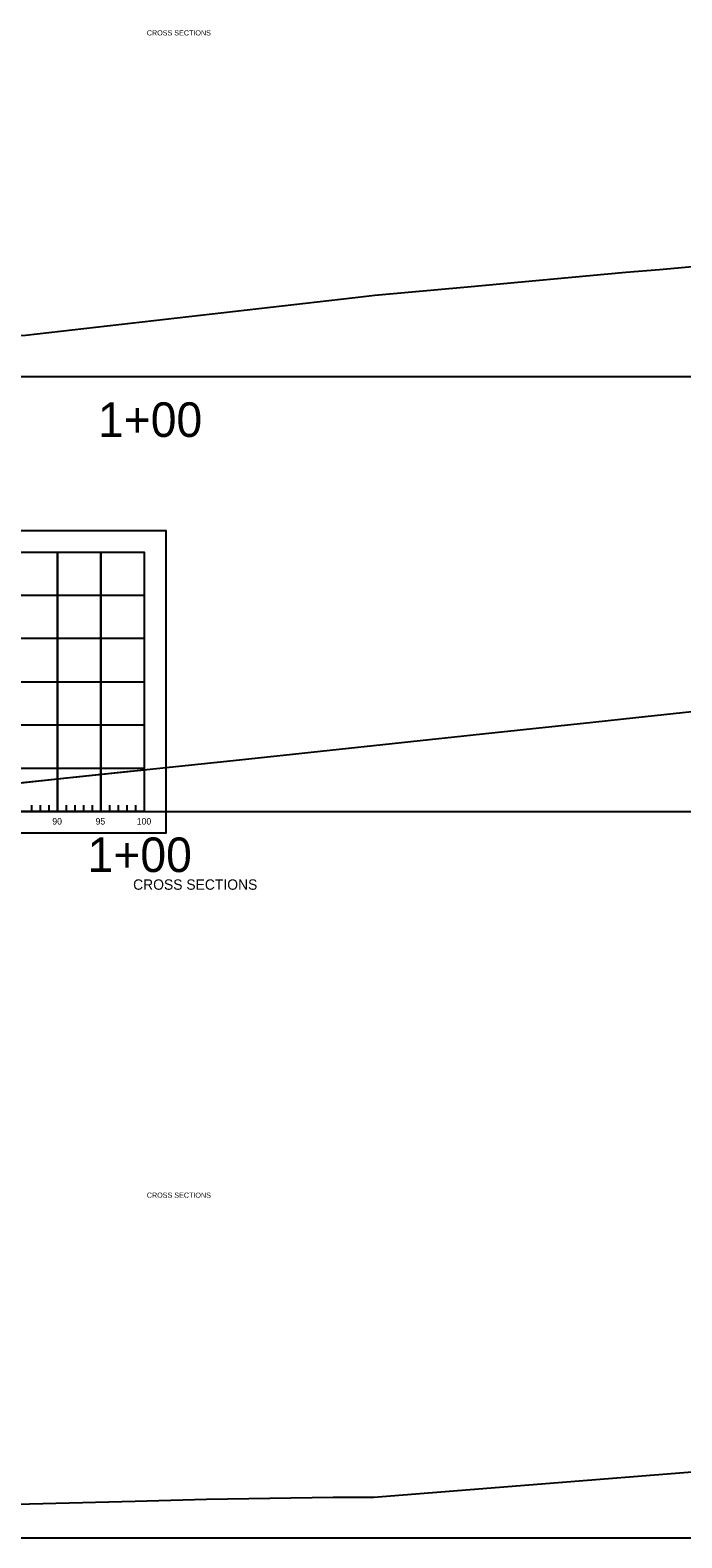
# Model space of a CAD drawing. Extents: x 1578769 to 1579225, y 724002 to 724828.
# Drawn here: x 1578926.9 to 1579002.2, y 724303.2 to 724477.5 of the extents above; entities that cross this region are included whole.
import ezdxf

# ---------------------------------------------------------------- set-up
doc = ezdxf.new("R2010")
doc.units = 0
for name, color, linetype in [('1', 7, 'Continuous'), ('Default', 7, 'Continuous'), ('Old_Level_1', 7, 'Continuous'), ('Old_Level_41', 7, 'Continuous'), ('Old_Level_42', 7, 'Continuous'), ('R_Border', 7, 'Continuous'), ('R_Exist Surface', 7, 'Continuous')]:
    doc.layers.add(name, color=color, linetype=linetype)

msp = doc.modelspace()

# ---------------------------------------------------------------- linework, layer by layer
at = {"layer": 'Default'}
for p, q in [((1578841.23, 724437.47), (1579141.23, 724437.47)), ((1578840.03, 724387.15), (1579140.03, 724387.15)), ((1578824.19, 724303.15), (1579224.19, 724303.15))]:
    msp.add_line(p, q, dxfattribs=at)
for points in [[(1578841.23, 724457.07), (1578842.26, 724457.06), (1578863.33, 724456.94), (1578874.29, 724456.89), (1578876.4, 724454.8), (1578883.17, 724446.78), (1578901.02, 724441.71), (1578903.45, 724441.03), (1578909.92, 724441.38), (1578926.32, 724442.25), (1578964.09, 724446.55), (1578966.7, 724446.87), (1578977.39, 724447.84), (1578995.69, 724449.51), (1578999.6, 724449.84), (1579038.5, 724453.37)], [(1578840.03, 724407.28), (1578843.97, 724407.18), (1578868.72, 724406.96), (1578870.69, 724406.94), (1578871.02, 724406.55), (1578881.3, 724394.25), (1578887.04, 724393.8), (1578904.53, 724392.22), (1578918.75, 724390.98), (1578924.86, 724390.39), (1578951.06, 724393.14), (1578979.15, 724396.13), (1578991.89, 724397.48), (1578996.87, 724398.01), (1579008.38, 724399.25), (1579066.25, 724403.44), (1579074.56, 724404.15)], [(1578822.94, 724322.15), (1578824.35, 724322.1), (1578827.25, 724322.09), (1578831.42, 724322.06), (1578836.82, 724322.03), (1578858.59, 724322.07), (1578861.13, 724322.07), (1578862.94, 724322.07), (1578882.45, 724322.01), (1578884.52, 724320.41), (1578890.39, 724312.8), (1578905.44, 724309.39), (1578918.12, 724306.85), (1578923.76, 724307), (1578939, 724307.39), (1578947.24, 724307.61), (1578961.87, 724307.85), (1578966.59, 724307.87), (1579023.72, 724312.41), (1579059.08, 724315.37), (1579126.24, 724320.04), (1579145.79, 724321.28)]]:
    msp.add_lwpolyline(points, dxfattribs=at)
at = {"layer": 'Old_Level_1'}
msp.add_lwpolyline([(1578815.03, 724419.65), (1578942.53, 724419.65), (1578942.53, 724384.65), (1578815.03, 724384.65)], close=True, dxfattribs=at)
msp.add_lwpolyline([(1578820.03, 724417.15), (1578940.03, 724417.15), (1578940.03, 724387.15), (1578820.03, 724387.15)], dxfattribs=at)
at = {"layer": 'Old_Level_41'}
for p, q in [((1578930.03, 724387.15), (1578930.03, 724417.15)), ((1578930.03, 724417.15), (1578930.03, 724387.15)), ((1578935.03, 724387.15), (1578935.03, 724417.15)), ((1578935.03, 724417.15), (1578935.03, 724387.15))]:
    msp.add_line(p, q, dxfattribs=at)
for points in [[(1578940.03, 724412.15), (1578820.03, 724412.15)], [(1578940.03, 724407.15), (1578820.03, 724407.15)], [(1578820.03, 724402.15), (1578940.03, 724402.15)], [(1578940.03, 724397.15), (1578820.03, 724397.15)], [(1578820.03, 724392.15), (1578940.03, 724392.15)]]:
    msp.add_lwpolyline(points, dxfattribs=at)
at = {"layer": 'Old_Level_42'}
for p, q in [((1578927.03, 724387.9), (1578927.03, 724387.15)), ((1578928.03, 724387.9), (1578928.03, 724387.15)), ((1578929.03, 724387.9), (1578929.03, 724387.15)), ((1578931.03, 724387.9), (1578931.03, 724387.15)), ((1578932.03, 724387.9), (1578932.03, 724387.15)), ((1578933.03, 724387.9), (1578933.03, 724387.15)), ((1578934.03, 724387.9), (1578934.03, 724387.15)), ((1578936.03, 724387.9), (1578936.03, 724387.15)), ((1578937.03, 724387.9), (1578937.03, 724387.15)), ((1578938.03, 724387.9), (1578938.03, 724387.15)), ((1578939.03, 724387.9), (1578939.03, 724387.15))]:
    msp.add_line(p, q, dxfattribs=at)
at = {"layer": 'R_Exist Surface'}
msp.add_lwpolyline([(1578820.03, 724407.31), (1578840.09, 724407.3), (1578856.16, 724407.11), (1578866.05, 724406.98), (1578870.1, 724406.95), (1578871.12, 724406.48), (1578874.09, 724402.86), (1578881.07, 724394.63), (1578882.07, 724394.22), (1578883.09, 724394.14), (1578888.06, 724393.7), (1578893.09, 724393.29), (1578898.08, 724392.85), (1578907.06, 724392.01), (1578915.07, 724391.3), (1578925.13, 724390.4), (1578931.08, 724391.04), (1578938.04, 724391.76), (1578940.03, 724391.96)], dxfattribs=at)

# ---------------------------------------------------------------- texts
at = {"layer": '1'}
for s, p in [('90', (1578929.42, 724385.64)), ('95', (1578934.42, 724385.64)), ('100', (1578939.18, 724385.64))]:
    msp.add_text(s, height=0.75, dxfattribs=at).set_placement(p)
at = {"layer": 'Default'}
for p in [(1578934.7, 724430.47), (1578933.5, 724380.15)]:
    msp.add_text('1+00', height=4, dxfattribs=at).set_placement(p)
at = {"layer": 'R_Border'}
for height, p in [(0.6, (1578940.34, 724476.9)), (1.2, (1578938.76, 724378.1)), (0.6, (1578940.34, 724342.48))]:
    msp.add_text('CROSS SECTIONS', height=height, dxfattribs=at).set_placement(p)

doc.saveas('drawing.dxf')
